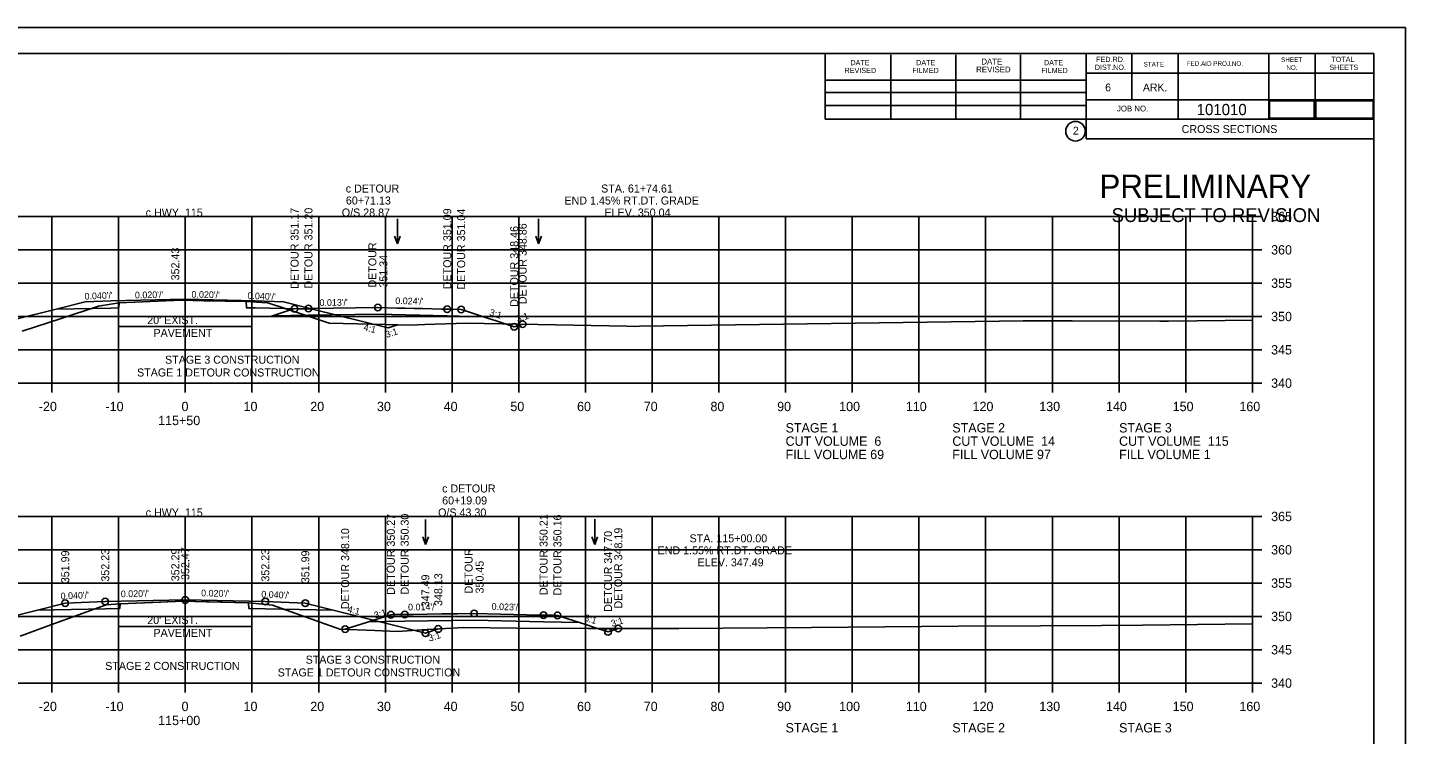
# Model space of a CAD drawing. Extents: x 1630712 to 1632516, y 782146 to 785403.
# Drawn here: x 1632309.3 to 1632515.9, y 785083.9 to 785190 of the extents above; entities that cross this region are included whole.
import ezdxf

# ---------------------------------------------------------------- set-up
doc = ezdxf.new("R2010")
doc.units = 0
for name, color, linetype in [('Notes', 7, 'Continuous'), ('Page Number', 7, 'Continuous'), ('R_Alt Surface', 7, 'Continuous'), ('R_Axis', 7, 'Continuous'), ('R_Axis Annot', 7, 'Continuous'), ('R_Border', 7, 'Continuous'), ('R_Border Notes', 7, 'Continuous'), ('R_Border Prem', 7, 'Continuous'), ('R_Detour Subgrade', 7, 'Continuous'), ('R_Detour Surface', 7, 'Continuous'), ('R_Exist Surface', 7, 'Continuous'), ('R_Fin Surface', 7, 'Continuous'), ('R_Grid', 7, 'Continuous'), ('R_No Plot', 7, 'Continuous'), ('R_Water Annot', 7, 'Continuous'), ('R_Xsect Elev', 7, 'Continuous'), ('R_Xsect Elev Detour', 7, 'Continuous'), ('R_Xsect Slope', 7, 'Continuous'), ('Total_Pages', 7, 'Continuous')]:
    doc.layers.add(name, color=color, linetype=linetype)

msp = doc.modelspace()

# ---------------------------------------------------------------- linework, layer by layer
at = {"layer": 'Notes'}
for p, q in [((1632322.96, 785143.45), (1632322.96, 785146.85)), ((1632342.96, 785143.45), (1632342.96, 785146.85)), ((1632322.96, 785145.15), (1632342.96, 785145.15)), ((1632322.96, 785098.45), (1632322.96, 785101.85)), ((1632342.96, 785098.45), (1632342.96, 785101.85)), ((1632322.96, 785100.15), (1632342.96, 785100.15))]:
    msp.add_line(p, q, dxfattribs=at)
at = {"layer": 'Page Number'}
msp.add_lwpolyline([(1632495.54, 785176.38), (1632502.21, 785176.38), (1632502.21, 785179.02), (1632495.54, 785179.02)], close=True, dxfattribs=at)
at = {"layer": 'R_Alt Surface'}
for points in [[(1632313.58, 785147.76), (1632321.86, 785147.92), (1632323, 785147.95), (1632323.05, 785148.69), (1632332.38, 785149.08), (1632342.07, 785148.92), (1632342.12, 785147.97), (1632343.43, 785147.94), (1632352.01, 785147.77)], [(1632310.79, 785102.6), (1632320.96, 785102.8), (1632323.14, 785102.84), (1632323.19, 785103.55), (1632332.58, 785103.94), (1632342.42, 785103.69), (1632342.47, 785102.85), (1632344.96, 785102.8), (1632355.14, 785102.6)]]:
    msp.add_lwpolyline(points, dxfattribs=at)
at = {"layer": 'R_Axis'}
for p, q in [((1632492.96, 785136.65), (1632492.96, 785161.65)), ((1632494.36, 785161.65), (1632492.96, 785161.65)), ((1632494.36, 785156.65), (1632492.96, 785156.65)), ((1632494.36, 785151.65), (1632492.96, 785151.65)), ((1632494.36, 785146.65), (1632492.96, 785146.65)), ((1632494.36, 785141.65), (1632492.96, 785141.65)), ((1632212.96, 785136.65), (1632492.96, 785136.65)), ((1632312.96, 785135.25), (1632312.96, 785136.65)), ((1632322.96, 785135.25), (1632322.96, 785136.65)), ((1632332.96, 785135.25), (1632332.96, 785136.65)), ((1632342.96, 785135.25), (1632342.96, 785136.65)), ((1632352.96, 785135.25), (1632352.96, 785136.65)), ((1632362.96, 785135.25), (1632362.96, 785136.65)), ((1632372.96, 785135.25), (1632372.96, 785136.65)), ((1632382.96, 785135.25), (1632382.96, 785136.65)), ((1632392.96, 785135.25), (1632392.96, 785136.65)), ((1632402.96, 785135.25), (1632402.96, 785136.65)), ((1632412.96, 785135.25), (1632412.96, 785136.65)), ((1632422.96, 785135.25), (1632422.96, 785136.65)), ((1632432.96, 785135.25), (1632432.96, 785136.65)), ((1632442.96, 785135.25), (1632442.96, 785136.65)), ((1632452.96, 785135.25), (1632452.96, 785136.65)), ((1632462.96, 785135.25), (1632462.96, 785136.65)), ((1632472.96, 785135.25), (1632472.96, 785136.65)), ((1632482.96, 785135.25), (1632482.96, 785136.65)), ((1632492.96, 785135.25), (1632492.96, 785136.65)), ((1632494.36, 785136.65), (1632492.96, 785136.65)), ((1632492.96, 785091.65), (1632492.96, 785116.65)), ((1632494.36, 785116.65), (1632492.96, 785116.65)), ((1632494.36, 785111.65), (1632492.96, 785111.65)), ((1632494.36, 785106.65), (1632492.96, 785106.65)), ((1632494.36, 785101.65), (1632492.96, 785101.65)), ((1632494.36, 785096.65), (1632492.96, 785096.65)), ((1632212.96, 785091.65), (1632492.96, 785091.65)), ((1632312.96, 785090.25), (1632312.96, 785091.65)), ((1632322.96, 785090.25), (1632322.96, 785091.65)), ((1632332.96, 785090.25), (1632332.96, 785091.65)), ((1632342.96, 785090.25), (1632342.96, 785091.65)), ((1632352.96, 785090.25), (1632352.96, 785091.65)), ((1632362.96, 785090.25), (1632362.96, 785091.65)), ((1632372.96, 785090.25), (1632372.96, 785091.65)), ((1632382.96, 785090.25), (1632382.96, 785091.65)), ((1632392.96, 785090.25), (1632392.96, 785091.65)), ((1632402.96, 785090.25), (1632402.96, 785091.65)), ((1632412.96, 785090.25), (1632412.96, 785091.65)), ((1632422.96, 785090.25), (1632422.96, 785091.65)), ((1632432.96, 785090.25), (1632432.96, 785091.65)), ((1632442.96, 785090.25), (1632442.96, 785091.65)), ((1632452.96, 785090.25), (1632452.96, 785091.65)), ((1632462.96, 785090.25), (1632462.96, 785091.65)), ((1632472.96, 785090.25), (1632472.96, 785091.65)), ((1632482.96, 785090.25), (1632482.96, 785091.65)), ((1632492.96, 785090.25), (1632492.96, 785091.65)), ((1632494.36, 785091.65), (1632492.96, 785091.65))]:
    msp.add_line(p, q, dxfattribs=at)
at = {"layer": 'R_Border'}
for p, q in [((1632194.96, 785186.11), (1632511.14, 785186.11)), ((1632347.48, 785185.85), (1632347.48, 785185.85)), ((1632347.48, 785185.85), (1632347.48, 785185.85)), ((1632428.88, 785176.23), (1632428.88, 785186.11)), ((1632438.74, 785176.23), (1632438.74, 785185.91)), ((1632448.5, 785176.23), (1632448.5, 785185.91)), ((1632458.18, 785176.23), (1632458.18, 785185.91)), ((1632468.04, 785186.11), (1632468.04, 785173.31)), ((1632474.88, 785186.11), (1632474.88, 785179.17)), ((1632481.82, 785186.11), (1632481.82, 785176.23)), ((1632495.4, 785186.11), (1632495.4, 785176.23)), ((1632502.34, 785186.11), (1632502.34, 785176.23)), ((1632511.14, 784980.65), (1632511.14, 785186.11)), ((1632428.88, 785182.09), (1632468.04, 785182.09)), ((1632511.14, 785183.17), (1632468.04, 785183.17)), ((1632511.14, 785183.19), (1632511.14, 785183.19)), ((1632428.88, 785180.23), (1632468.04, 785180.23)), ((1632428.88, 785176.23), (1632428.88, 785178.29)), ((1632428.88, 785178.29), (1632468.04, 785178.29)), ((1632511.14, 785179.17), (1632468.04, 785179.17)), ((1632471, 785179.17), (1632511.14, 785179.17)), ((1632511.14, 785176.23), (1632428.88, 785176.23)), ((1632468.04, 785173.31), (1632511.14, 785173.31))]:
    msp.add_line(p, q, dxfattribs=at)
msp.add_circle((1632466.43, 785174.44), 1.47, dxfattribs=at)
at = {"layer": 'R_Detour Subgrade'}
for points in [[(1632346.02, 785146.76), (1632351.43, 785146.84), (1632361.83, 785146.99), (1632372.24, 785146.74), (1632377.65, 785146.61)], [(1632360.45, 785100.86), (1632365.86, 785100.94), (1632376.27, 785101.1), (1632386.68, 785100.85), (1632392.08, 785100.73)]]:
    msp.add_lwpolyline(points, dxfattribs=at)
at = {"layer": 'R_Detour Surface'}
for points in [[(1632345.75, 785146.67), (1632346.02, 785146.76), (1632348.91, 785147.68), (1632349.35, 785147.81), (1632351.38, 785147.84), (1632351.43, 785147.84), (1632351.56, 785147.84), (1632351.84, 785147.85), (1632361.77, 785147.99), (1632361.83, 785147.99), (1632361.83, 785147.99), (1632361.83, 785147.99), (1632364.76, 785147.92), (1632365.91, 785147.89), (1632367.29, 785147.86), (1632368.54, 785147.83), (1632371.36, 785147.76), (1632372.24, 785147.74), (1632372.49, 785147.73), (1632374.32, 785147.69), (1632374.96, 785147.48), (1632377.65, 785146.61), (1632377.82, 785146.55), (1632378.27, 785146.4), (1632379.57, 785145.98), (1632382.28, 785145.1), (1632382.81, 785145.27), (1632383.54, 785145.5)], [(1632356.93, 785099.75), (1632359.33, 785100.51), (1632360.45, 785100.86), (1632362.96, 785101.66), (1632363.78, 785101.91), (1632364.21, 785101.92), (1632365.86, 785101.94), (1632367.15, 785101.96), (1632371.42, 785102.02), (1632372.4, 785102.04), (1632372.98, 785102.05), (1632373.77, 785102.06), (1632376.26, 785102.1), (1632376.27, 785102.1), (1632376.27, 785102.1), (1632384.17, 785101.91), (1632386.68, 785101.85), (1632388.01, 785101.82), (1632388.76, 785101.81), (1632390.17, 785101.35), (1632392.08, 785100.73), (1632392.39, 785100.63), (1632392.71, 785100.53), (1632394.75, 785099.86), (1632396.34, 785099.35), (1632396.83, 785099.5), (1632397.88, 785099.84)]]:
    msp.add_lwpolyline(points, dxfattribs=at)
at = {"layer": 'R_Exist Surface'}
for points in [[(1632308.53, 785144.47), (1632314.35, 785146.35), (1632319.95, 785148.21), (1632321.79, 785148.5), (1632323.05, 785148.69), (1632328.86, 785148.93), (1632332.38, 785149.08), (1632335.76, 785149.02), (1632342.07, 785148.92), (1632344.42, 785148.75), (1632345.36, 785148.68), (1632348.24, 785147.76), (1632354.53, 785145.66), (1632362.97, 785145.46), (1632366.69, 785145.37), (1632368.86, 785145.45), (1632375.14, 785145.67), (1632399.16, 785145.19), (1632400.45, 785145.17), (1632401.05, 785145.18), (1632458.6, 785145.99), (1632465.94, 785145.98), (1632479.05, 785145.96), (1632480.37, 785145.96), (1632488.87, 785146.07), (1632492.96, 785146.12)], [(1632308.22, 785098.67), (1632312.8, 785100.37), (1632321.08, 785103.37), (1632322.48, 785103.51), (1632323.19, 785103.55), (1632329.27, 785103.8), (1632332.58, 785103.94), (1632336.13, 785103.85), (1632342.42, 785103.69), (1632344.61, 785103.47), (1632346.04, 785103.32), (1632350.23, 785101.82), (1632356.13, 785099.74), (1632361.37, 785099.55), (1632364.71, 785099.4), (1632369.21, 785099.68), (1632374.74, 785099.99), (1632382.6, 785099.88), (1632393.37, 785099.82), (1632406.95, 785099.86), (1632426.86, 785100.01), (1632448.86, 785100.18), (1632461.2, 785100.24), (1632470.34, 785100.29), (1632476.49, 785100.32), (1632492.96, 785100.52)]]:
    msp.add_lwpolyline(points, dxfattribs=at)
at = {"layer": 'R_Fin Surface'}
for points in [[(1632298.32, 785144.39), (1632299.33, 785144.06), (1632301.04, 785144.63), (1632313.58, 785147.76), (1632317.93, 785148.85), (1632321.86, 785149.01), (1632332.96, 785149.23), (1632343.43, 785149.02), (1632347.68, 785148.85), (1632352.01, 785147.77), (1632363.36, 785144.93), (1632364.81, 785145.41)], [(1632290.9, 785098.97), (1632293.68, 785098.05), (1632296.96, 785099.14), (1632310.79, 785102.6), (1632314.96, 785103.64), (1632320.96, 785103.88), (1632332.96, 785104.12), (1632344.96, 785103.88), (1632350.96, 785103.64), (1632355.14, 785102.6), (1632368.96, 785099.14), (1632368.98, 785099.14), (1632370.89, 785099.77)]]:
    msp.add_lwpolyline(points, dxfattribs=at)
at = {"layer": 'R_Grid'}
for p, q in [((1632212.96, 785161.65), (1632492.96, 785161.65)), ((1632312.96, 785136.65), (1632312.96, 785161.65)), ((1632322.96, 785136.65), (1632322.96, 785161.65)), ((1632332.96, 785136.65), (1632332.96, 785161.65)), ((1632342.96, 785136.65), (1632342.96, 785161.65)), ((1632352.96, 785136.65), (1632352.96, 785161.65)), ((1632362.96, 785136.65), (1632362.96, 785161.65)), ((1632372.96, 785136.65), (1632372.96, 785161.65)), ((1632382.96, 785136.65), (1632382.96, 785161.65)), ((1632392.96, 785136.65), (1632392.96, 785161.65)), ((1632402.96, 785136.65), (1632402.96, 785161.65)), ((1632412.96, 785136.65), (1632412.96, 785161.65)), ((1632422.96, 785136.65), (1632422.96, 785161.65)), ((1632432.96, 785136.65), (1632432.96, 785161.65)), ((1632442.96, 785136.65), (1632442.96, 785161.65)), ((1632452.96, 785136.65), (1632452.96, 785161.65)), ((1632462.96, 785136.65), (1632462.96, 785161.65)), ((1632472.96, 785136.65), (1632472.96, 785161.65)), ((1632482.96, 785136.65), (1632482.96, 785161.65)), ((1632492.96, 785136.65), (1632492.96, 785161.65)), ((1632212.96, 785156.65), (1632492.96, 785156.65)), ((1632212.96, 785151.65), (1632492.96, 785151.65)), ((1632212.96, 785146.65), (1632492.96, 785146.65)), ((1632212.96, 785141.65), (1632492.96, 785141.65)), ((1632212.96, 785136.65), (1632492.96, 785136.65)), ((1632212.96, 785116.65), (1632492.96, 785116.65)), ((1632312.96, 785091.65), (1632312.96, 785116.65)), ((1632322.96, 785091.65), (1632322.96, 785116.65)), ((1632332.96, 785091.65), (1632332.96, 785116.65)), ((1632342.96, 785091.65), (1632342.96, 785116.65)), ((1632352.96, 785091.65), (1632352.96, 785116.65)), ((1632362.96, 785091.65), (1632362.96, 785116.65)), ((1632372.96, 785091.65), (1632372.96, 785116.65)), ((1632382.96, 785091.65), (1632382.96, 785116.65)), ((1632392.96, 785091.65), (1632392.96, 785116.65)), ((1632402.96, 785091.65), (1632402.96, 785116.65)), ((1632412.96, 785091.65), (1632412.96, 785116.65)), ((1632422.96, 785091.65), (1632422.96, 785116.65)), ((1632432.96, 785091.65), (1632432.96, 785116.65)), ((1632442.96, 785091.65), (1632442.96, 785116.65)), ((1632452.96, 785091.65), (1632452.96, 785116.65)), ((1632462.96, 785091.65), (1632462.96, 785116.65)), ((1632472.96, 785091.65), (1632472.96, 785116.65)), ((1632482.96, 785091.65), (1632482.96, 785116.65)), ((1632492.96, 785091.65), (1632492.96, 785116.65)), ((1632212.96, 785111.65), (1632492.96, 785111.65)), ((1632212.96, 785106.65), (1632492.96, 785106.65)), ((1632212.96, 785101.65), (1632492.96, 785101.65)), ((1632212.96, 785096.65), (1632492.96, 785096.65)), ((1632212.96, 785091.65), (1632492.96, 785091.65))]:
    msp.add_line(p, q, dxfattribs=at)
at = {"layer": 'R_No Plot'}
msp.add_line((1632182.56, 785190), (1632515.9, 785190), dxfattribs=at)
msp.add_lwpolyline([(1632182.56, 785190), (1632515.9, 785190), (1632515.9, 784976.66), (1632182.56, 784976.66)], close=True, dxfattribs=at)
for centre in [(1632361.83, 785147.99), (1632349.35, 785147.81), (1632351.43, 785147.84), (1632372.24, 785147.74), (1632374.32, 785147.69), (1632382.28, 785145.1), (1632383.54, 785145.5), (1632314.96, 785103.64), (1632320.96, 785103.88), (1632332.96, 785104.12), (1632344.96, 785103.88), (1632350.96, 785103.64), (1632363.78, 785101.91), (1632365.86, 785101.94), (1632376.27, 785102.1), (1632386.68, 785101.85), (1632388.76, 785101.81), (1632356.93, 785099.75), (1632368.96, 785099.14), (1632368.98, 785099.14), (1632370.89, 785099.77), (1632396.34, 785099.35), (1632397.88, 785099.84)]:
    msp.add_circle(centre, 0.5, dxfattribs=at)
at = {"layer": 'R_Water Annot'}
for p, q in [((1632364.76, 785161.3), (1632364.76, 785157.53)), ((1632385.93, 785161.3), (1632385.93, 785157.53)), ((1632364.76, 785157.53), (1632364.34, 785158.68)), ((1632364.76, 785157.53), (1632365.18, 785158.68)), ((1632385.93, 785157.53), (1632385.51, 785158.68)), ((1632385.93, 785157.53), (1632386.35, 785158.68)), ((1632368.99, 785116.19), (1632368.99, 785112.42)), ((1632394.35, 785116.22), (1632394.35, 785112.45)), ((1632368.99, 785112.42), (1632368.57, 785113.57)), ((1632368.99, 785112.42), (1632369.41, 785113.57)), ((1632394.35, 785112.45), (1632393.93, 785113.6)), ((1632394.35, 785112.45), (1632394.77, 785113.6))]:
    msp.add_line(p, q, dxfattribs=at)
at = {"layer": 'Total_Pages'}
msp.add_lwpolyline([(1632502.44, 785176.38), (1632511.05, 785176.38), (1632511.05, 785179.02), (1632502.44, 785179.02)], close=True, dxfattribs=at)

# ---------------------------------------------------------------- texts
at = {"layer": 'Notes'}
for s, p in [('c DETOUR', (1632357.02, 785165.25)), ('STA. 61+74.61', (1632395.31, 785165.25)), ('60+71.13', (1632357.04, 785163.45)), ('END 1.45% RT.DT. GRADE', (1632389.81, 785163.45)), ('c HWY. 115', (1632327.02, 785161.65)), ('O/S 28.87', (1632356.43, 785161.65)), ('ELEV. 350.04', (1632395.81, 785161.65)), ("20' EXIST.", (1632327.26, 785145.51)), ('PAVEMENT', (1632328.19, 785143.59)), ('STAGE 3 CONSTRUCTION', (1632329.93, 785139.57)), ('STAGE 1 DETOUR CONSTRUCTION', (1632325.73, 785137.65)), ('c DETOUR', (1632371.46, 785120.25)), ('60+19.09', (1632371.47, 785118.45)), ('c HWY. 115', (1632327.02, 785116.65)), ('O/S 43.30', (1632370.87, 785116.65)), ('STA. 115+00.00', (1632408.57, 785112.77)), ('END 1.55% RT.DT. GRADE', (1632403.77, 785110.97)), ('ELEV. 347.49', (1632409.77, 785109.17)), ("20' EXIST.", (1632327.26, 785100.51)), ('PAVEMENT', (1632328.19, 785098.59)), ('STAGE 2 CONSTRUCTION', (1632320.96, 785093.63)), ('STAGE 3 CONSTRUCTION', (1632351.01, 785094.57)), ('STAGE 1 DETOUR CONSTRUCTION', (1632346.81, 785092.65))]:
    msp.add_text(s, height=1.2, dxfattribs=at).set_placement(p)
at = {"layer": 'R_Axis Annot'}
for s, p in [('365', (1632495.76, 785160.95)), ('360', (1632495.76, 785155.95)), ('355', (1632495.76, 785150.95)), ('350', (1632495.76, 785145.95)), ('345', (1632495.76, 785140.95)), ('340', (1632495.76, 785135.95)), ('-20', (1632311, 785132.45)), ('-10', (1632321, 785132.45)), ('0', (1632332.4, 785132.45)), ('10', (1632341.7, 785132.45)), ('20', (1632351.7, 785132.45)), ('30', (1632361.7, 785132.45)), ('40', (1632371.7, 785132.45)), ('50', (1632381.7, 785132.45)), ('60', (1632391.7, 785132.45)), ('70', (1632401.7, 785132.45)), ('80', (1632411.7, 785132.45)), ('90', (1632421.7, 785132.45)), ('100', (1632431, 785132.45)), ('110', (1632441, 785132.45)), ('120', (1632451, 785132.45)), ('130', (1632461, 785132.45)), ('140', (1632471, 785132.45)), ('150', (1632481, 785132.45)), ('160', (1632491, 785132.45)), ('115+50', (1632328.9, 785130.35)), ('STAGE 1', (1632422.96, 785129.25)), ('STAGE 2', (1632447.96, 785129.25)), ('STAGE 3', (1632472.96, 785129.25)), ('CUT VOLUME  6', (1632422.96, 785127.25)), ('CUT VOLUME  14', (1632447.96, 785127.25)), ('CUT VOLUME  115', (1632472.96, 785127.25)), ('FILL VOLUME 69', (1632422.96, 785125.25)), ('FILL VOLUME 97', (1632447.96, 785125.25)), ('FILL VOLUME 1', (1632472.96, 785125.25)), ('365', (1632495.76, 785115.95)), ('360', (1632495.76, 785110.95)), ('355', (1632495.76, 785105.95)), ('350', (1632495.76, 785100.95)), ('345', (1632495.76, 785095.95)), ('340', (1632495.76, 785090.95)), ('-20', (1632311, 785087.45)), ('-10', (1632321, 785087.45)), ('0', (1632332.4, 785087.45)), ('10', (1632341.7, 785087.45)), ('20', (1632351.7, 785087.45)), ('30', (1632361.7, 785087.45)), ('40', (1632371.7, 785087.45)), ('50', (1632381.7, 785087.45)), ('60', (1632391.7, 785087.45)), ('70', (1632401.7, 785087.45)), ('80', (1632411.7, 785087.45)), ('90', (1632421.7, 785087.45)), ('100', (1632431, 785087.45)), ('110', (1632441, 785087.45)), ('120', (1632451, 785087.45)), ('130', (1632461, 785087.45)), ('140', (1632471, 785087.45)), ('150', (1632481, 785087.45)), ('160', (1632491, 785087.45)), ('115+00', (1632328.9, 785085.35)), ('STAGE 1', (1632422.96, 785084.25)), ('STAGE 2', (1632447.96, 785084.25)), ('STAGE 3', (1632472.96, 785084.25))]:
    msp.add_text(s, height=1.4, dxfattribs=at).set_placement(p)
at = {"layer": 'R_Border'}
for s, height, p in [('REVISED', 0.782, (1632431.8, 785183.17)), ('DATE', 0.782, (1632432.68, 785184.35)), ('FILMED', 0.782, (1632441.96, 785183.17)), ('DATE', 0.782, (1632442.54, 785184.35)), ('REVISED', 0.879, (1632451.54, 785183.27)), ('DATE', 0.879, (1632452.32, 785184.45)), ('FILMED', 0.782, (1632461.3, 785183.17)), ('DATE', 0.782, (1632461.7, 785184.35)), ('DIST.NO.', 0.782, (1632469.32, 785183.65)), ('FED.RD.', 0.782, (1632469.52, 785184.83)), ('STATE', 0.684, (1632476.64, 785184.15)), ('FED.AID PROJ.NO.', 0.684, (1632483.1, 785184.25)), ('SHEET', 0.684, (1632497.26, 785184.83)), ('NO.', 0.684, (1632498.04, 785183.65)), ('SHEETS', 0.782, (1632504.5, 785183.65)), ('TOTAL', 0.782, (1632504.78, 785184.83)), ('6', 1.17, (1632470.88, 785180.43)), ('ARK.', 1.172, (1632476.54, 785180.43)), ('JOB NO.', 0.879, (1632472.64, 785177.41)), ('2', 1.17, (1632466.05, 785173.95))]:
    msp.add_text(s, height=height, rotation=360, dxfattribs=at).set_placement(p)
at = {"layer": 'R_Border Notes'}
for s, height, p in [('101010', 1.68, (1632484.6, 785176.86)), ('CROSS SECTIONS', 1.2, (1632482.34, 785174.17))]:
    msp.add_text(s, height=height, dxfattribs=at).set_placement(p)
at = {"layer": 'R_Border Prem'}
for s, height, p in [('PRELIMINARY', 3.5, (1632470.03, 785164.45)), ('SUBJECT TO REVISION', 2.0751, (1632471.84, 785160.82))]:
    msp.add_text(s, height=height, rotation=360, dxfattribs=at).set_placement(p)
at = {"layer": 'R_Xsect Elev'}
for s, p in [('352.43', (1632332.06, 785152.07)), ('351.99', (1632315.56, 785106.64)), ('352.23', (1632321.56, 785106.88)), ('352.29', (1632332.06, 785106.93)), ('352.47', (1632333.56, 785107.12)), ('352.23', (1632345.56, 785106.88)), ('351.99', (1632351.56, 785106.64)), ('  347.49', (1632369.56, 785102.14)), (' 348.13', (1632371.49, 785102.77))]:
    msp.add_text(s, height=1.2, rotation=90, dxfattribs=at).set_placement(p)
at = {"layer": 'R_Xsect Elev Detour'}
for s, p in [('DETOUR 351.17', (1632349.95, 785150.81)), ('DETOUR 351.20', (1632352.03, 785150.84)), ('DETOUR 351.09', (1632372.84, 785150.74)), ('DETOUR 351.04', (1632374.92, 785150.69)), ('DETOUR 348.46', (1632382.88, 785148.1)), ('DETOUR 348.86', (1632384.14, 785148.5)), ('DETOUR', (1632361.61, 785150.99)), ('351.34', (1632363.26, 785150.99)), ('DETOUR 350.27', (1632364.38, 785104.91)), ('DETOUR 350.30', (1632366.46, 785104.94)), ('DETOUR 350.21', (1632387.28, 785104.85)), ('DETOUR 350.16', (1632389.36, 785104.81)), ('DETOUR 348.10', (1632357.53, 785102.75)), ('DETOUR 347.70', (1632396.94, 785102.35)), ('DETOUR 348.19', (1632398.48, 785102.84)), ('DETOUR', (1632376.04, 785105.1)), ('350.45', (1632377.69, 785105.1))]:
    msp.add_text(s, height=1.2, rotation=90, dxfattribs=at).set_placement(p)
at = {"layer": 'R_Xsect Slope'}
for s, rotation, p in [("0.040'/'", 2.2906, (1632317.87, 785149.18)), ("0.020'/'", 1.1458, (1632325.42, 785149.36)), ("0.020'/'", 358.8542, (1632333.89, 785149.48)), ("0.040'/'", 357.7094, (1632342.27, 785149.29)), ("0.013'/'", 0.8083, (1632353.09, 785148.22)), ("0.024'/'", 358.6157, (1632364.44, 785148.53)), ('3:1', 341.9853, (1632378.46, 785146.87)), ('3:1', 17.5967, (1632382.76, 785145.78)), ('4:1', 345.9638, (1632359.61, 785144.6)), ('3:1', 18.4349, (1632363.15, 785143.42)), ("0.040'/'", 2.2906, (1632314.29, 785104.21)), ("0.020'/'", 1.1458, (1632323.3, 785104.53)), ("0.020'/'", 358.8542, (1632335.33, 785104.67)), ("0.040'/'", 357.7094, (1632344.34, 785104.5)), ('4:1', 345.9638, (1632357.21, 785102.3)), ("0.014'/'", 0.8433, (1632366.37, 785102.55)), ("0.023'/'", 358.6657, (1632378.88, 785102.64)), ('3:1', 17.5302, (1632361.44, 785101.31)), ('3:1', 342.0305, (1632392.7, 785101.05)), ('3:1', 17.5513, (1632396.96, 785100.07)), ('3:1', 18.4349, (1632369.59, 785097.86))]:
    msp.add_text(s, height=1, rotation=rotation, dxfattribs=at).set_placement(p)

doc.saveas('drawing.dxf')
